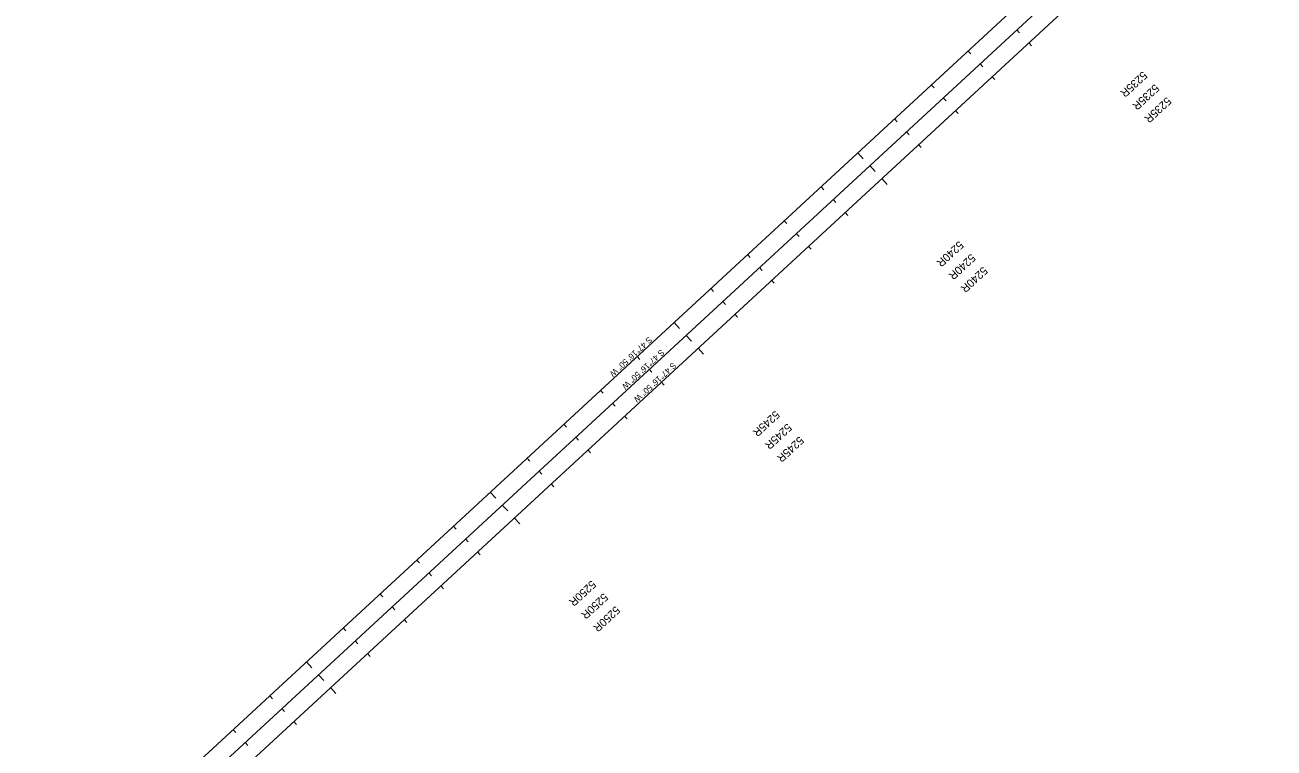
# Model space of a CAD drawing. Extents: x 2161211 to 2175594, y 601812 to 617732.
# Drawn here: x 2165467 to 2167964, y 607997 to 609442 of the extents above; entities that cross this region are included whole.
import ezdxf

# ---------------------------------------------------------------- set-up
doc = ezdxf.new("R2010")
doc.units = 0
for name, color, linetype in [('RD_HC_CL_Rel', 7, 'Continuous'), ('RD_HC_Data_Rel', 7, 'Continuous'), ('RD_HC_Data_Tic_Rel', 7, 'Continuous'), ('RD_HC_TX_Rel_Sta50', 7, 'Continuous')]:
    doc.layers.add(name, color=color, linetype=linetype)

msp = doc.modelspace()

# ---------------------------------------------------------------- linework, layer by layer
at = {"layer": 'RD_HC_CL_Rel'}
for p, q in [((2167916, 609910.7), (2165466.8, 607649.1)), ((2167939.8, 609884.8), (2165490.6, 607623.3)), ((2167963.7, 609859.1), (2165514.5, 607597.4))]:
    msp.add_line(p, q, dxfattribs=at)
at = {"layer": 'RD_HC_Data_Tic_Rel'}
for p, q in [((2167449.5, 609432.1), (2167454.9, 609426.2)), ((2167473.6, 609406.5), (2167479, 609400.6)), ((2167352, 609390), (2167357.5, 609384.1)), ((2167376, 609364.3), (2167381.5, 609358.4)), ((2167400.1, 609338.6), (2167405.5, 609332.8)), ((2167278.6, 609322.1), (2167284, 609316.3)), ((2167302.6, 609296.4), (2167308, 609290.6)), ((2167205.1, 609254.3), (2167210.5, 609248.4)), ((2167326.6, 609270.8), (2167332.1, 609264.9)), ((2167229.1, 609228.6), (2167234.5, 609222.7)), ((2167253.2, 609203), (2167258.6, 609197.1)), ((2167131.6, 609186.4), (2167142.5, 609174.7)), ((2167155.6, 609160.8), (2167166.5, 609149)), ((2167179.7, 609135.1), (2167190.6, 609123.4)), ((2167058.2, 609118.6), (2167063.6, 609112.7)), ((2167082.2, 609092.9), (2167087.6, 609087)), ((2167106.2, 609067.3), (2167111.7, 609061.4)), ((2166984.7, 609050.8), (2166990.1, 609044.9)), ((2167008.7, 609025.1), (2167014.1, 609019.2)), ((2166911.2, 608982.9), (2166916.6, 608977)), ((2167032.8, 608999.4), (2167038.2, 608993.6)), ((2166935.2, 608957.2), (2166940.6, 608951.4)), ((2166959.3, 608931.6), (2166964.7, 608925.7)), ((2166837.8, 608915.1), (2166843.2, 608909.2)), ((2166861.8, 608889.4), (2166867.2, 608883.5)), ((2166885.8, 608863.8), (2166891.3, 608857.9)), ((2166764.3, 608847.2), (2166775.1, 608835.5)), ((2166788.3, 608821.5), (2166799.1, 608809.8)), ((2166690.8, 608779.4), (2166696.2, 608773.5)), ((2166812.4, 608795.9), (2166823.2, 608784.2)), ((2166714.8, 608753.7), (2166720.2, 608747.8)), ((2166738.9, 608728.1), (2166744.3, 608722.2)), ((2166617.3, 608711.6), (2166622.8, 608705.7)), ((2166641.3, 608685.9), (2166646.8, 608680)), ((2166665.4, 608660.2), (2166670.9, 608654.4)), ((2166543.9, 608643.7), (2166549.3, 608637.8)), ((2166567.9, 608618), (2166573.3, 608612.1)), ((2166592, 608592.4), (2166597.4, 608586.5)), ((2166470.4, 608575.9), (2166475.8, 608570)), ((2166494.4, 608550.2), (2166499.8, 608544.3)), ((2166396.9, 608508), (2166407.8, 608496.3)), ((2166518.5, 608524.5), (2166523.9, 608518.7)), ((2166420.9, 608482.3), (2166431.8, 608470.6)), ((2166445, 608456.7), (2166455.9, 608445)), ((2166323.5, 608440.2), (2166328.9, 608434.3)), ((2166347.5, 608414.5), (2166352.9, 608408.6)), ((2166371.6, 608388.9), (2166377, 608383)), ((2166250, 608372.4), (2166255.4, 608366.5)), ((2166274, 608346.7), (2166279.4, 608340.8)), ((2166176.5, 608304.5), (2166182, 608298.6)), ((2166298.1, 608321), (2166303.5, 608315.1)), ((2166200.5, 608278.8), (2166206, 608272.9)), ((2166103.1, 608236.7), (2166108.5, 608230.8)), ((2166224.6, 608253.2), (2166230, 608247.3)), ((2166127.1, 608211), (2166132.5, 608205.1)), ((2166151.2, 608185.3), (2166156.6, 608179.5)), ((2166029.6, 608168.8), (2166040.5, 608157.1)), ((2166053.6, 608143.1), (2166064.5, 608131.4)), ((2166077.7, 608117.5), (2166088.5, 608105.7)), ((2165956.1, 608101), (2165961.6, 608095.1)), ((2165980.1, 608075.3), (2165985.6, 608069.4)), ((2165882.7, 608033.2), (2165888.1, 608027.3)), ((2166004.2, 608049.7), (2166009.6, 608043.8)), ((2165906.7, 608007.5), (2165912.1, 608001.6))]:
    msp.add_line(p, q, dxfattribs=at)

# ---------------------------------------------------------------- texts
at = {"layer": 'RD_HC_Data_Rel'}
for rotation, p in [(222.7194, (2166713.8, 608819.7)), (222.7195, (2166738.3, 608794.4)), (222.7194, (2166761.9, 608768.4))]:
    msp.add_text('S 47°16\' 50" W', height=12, rotation=rotation, dxfattribs=at).set_placement(p)
at = {"layer": 'RD_HC_TX_Rel_Sta50'}
for s, rotation, p in [('5235R', 222.7194, (2167701.4, 609350.5)), ('5235R', 222.7195, (2167725.4, 609324.8)), ('5235R', 222.7194, (2167749.5, 609299.2)), ('5240R', 222.7194, (2167334.1, 609011.3)), ('5240R', 222.7195, (2167358.1, 608985.6)), ('5240R', 222.7194, (2167382.2, 608960)), ('5245R', 222.7194, (2166966.7, 608672.1)), ('5245R', 222.7195, (2166990.7, 608646.4)), ('5245R', 222.7194, (2167014.8, 608620.8)), ('5250R', 222.7194, (2166599.4, 608332.9)), ('5250R', 222.7195, (2166623.4, 608307.2)), ('5250R', 222.7194, (2166647.5, 608281.6))]:
    msp.add_text(s, height=16, rotation=rotation, dxfattribs=at).set_placement(p)

doc.saveas('drawing.dxf')
